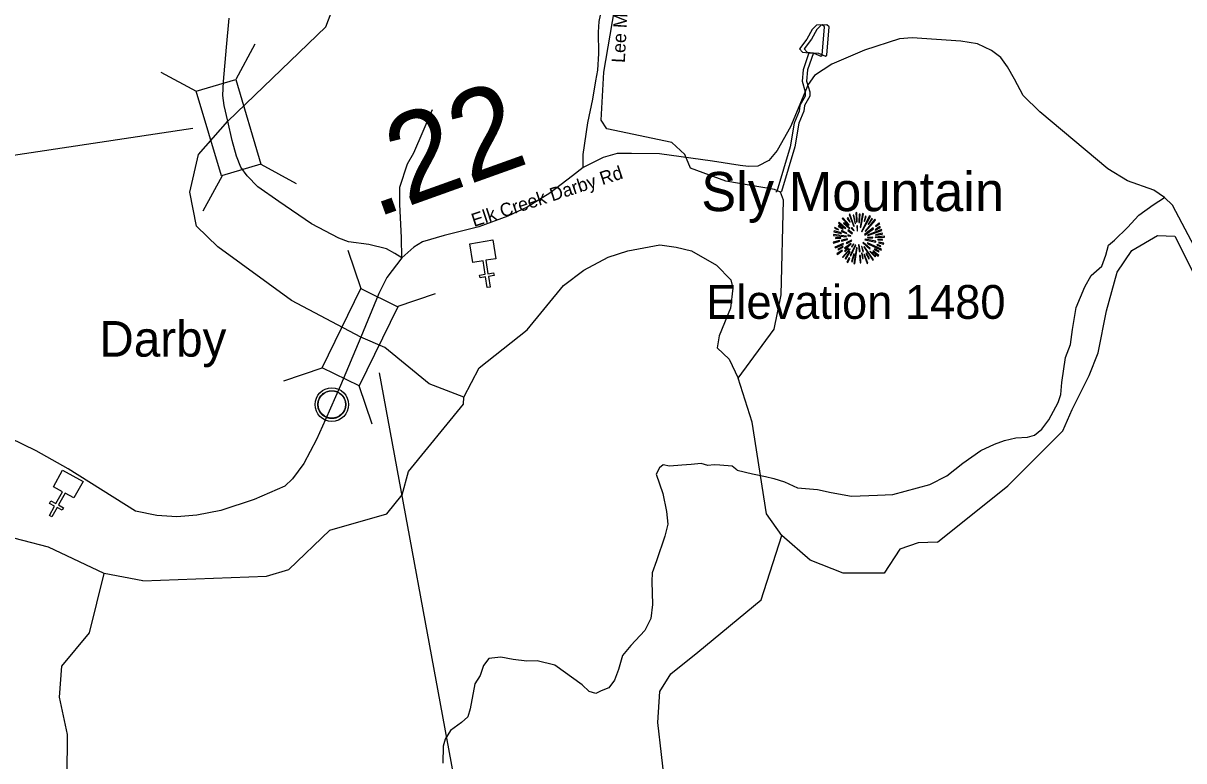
# Model space of a CAD drawing. Extents: x 1248089 to 1457196, y 820910 to 988753.
# Drawn here: x 1261020 to 1267538, y 869456 to 873600 of the extents above; entities that cross this region are included whole.
import ezdxf

# ---------------------------------------------------------------- set-up
doc = ezdxf.new("R2010")
doc.units = 0
for name, color, linetype in [('Exist Civil Demographics Community CELL', 7, 'Continuous'), ('Exist Civil Demographics Community Label', 7, 'Continuous'), ('Exist Cultural Church CELL', 7, 'Continuous'), ('Exist Geographical Mountain Summit CELL', 7, 'Continuous'), ('Exist Geographical Mountain Summit Elevation Number Label', 7, 'Continuous'), ('Exist Geographical Mountain Summit Label', 7, 'Continuous'), ('Exist Hydrographic Creek Single Shore', 7, 'Continuous'), ('Exist Hydrographic Misc Water Feature', 7, 'Continuous'), ('Exist Road Non-System Type 51', 7, 'Continuous'), ('Exist Road Secondary Structure Standard Bridge CELL', 7, 'Continuous'), ('Exist Road Secondary Structure Standard Bridge Number Label', 7, 'Continuous'), ('Exist Road Secondary Type 41 Attributed', 7, 'Continuous'), ('Exist Road Secondary Type 51 Attributed', 7, 'Continuous'), ('Exist Road Secondary Type 51 Label', 7, 'Continuous'), ('Prop GRAU CAT1 Cell', 7, 'Continuous')]:
    doc.layers.add(name, color=color, linetype=linetype)

msp = doc.modelspace()

# ---------------------------------------------------------------- linework, layer by layer
at = {"layer": 'Exist Civil Demographics Community CELL'}
msp.add_lwpolyline([(1262675.7, 871469.8), (1262676.7, 871475.4), (1262678.5, 871482), (1262681.4, 871489.2), (1262684.3, 871494.9), (1262687.6, 871500.7), (1262691.4, 871505.8), (1262695.4, 871510.2), (1262700, 871514.8), (1262705.5, 871519.4), (1262710.9, 871523), (1262715.8, 871525.9), (1262720.9, 871528.3), (1262726.3, 871530.6), (1262731.9, 871532.5), (1262736.3, 871533.6), (1262741.1, 871534.3), (1262745.3, 871535.1), (1262751.6, 871535.3), (1262756.1, 871535.2), (1262761.7, 871535), (1262766.6, 871534.2), (1262771.5, 871533.2), (1262776.5, 871531.8), (1262781.7, 871529.9), (1262788.4, 871527), (1262794.6, 871523.5), (1262799.7, 871519.9), (1262804.8, 871515.9), (1262808.2, 871512.8), (1262812.3, 871508.4), (1262816.1, 871503.7), (1262819.2, 871499.1), (1262822.3, 871494.1), (1262824.8, 871488.9), (1262826.8, 871483.9), (1262828.4, 871478.9), (1262829.7, 871474.3), (1262830.8, 871468.3), (1262831.4, 871463.6), (1262831.7, 871457.6), (1262831.5, 871451.8), (1262830.9, 871446.1), (1262830, 871440.6), (1262828.3, 871434.5), (1262826.4, 871428.6), (1262824.1, 871423.6), (1262821, 871417.6), (1262817.7, 871412.2), (1262814.3, 871407.5), (1262810, 871402.8), (1262804.7, 871397.8), (1262799.7, 871393.7), (1262794.7, 871390.3), (1262790.4, 871387.8), (1262783.6, 871384.5), (1262776.4, 871381.8), (1262770.5, 871380.4), (1262763.9, 871379.1), (1262759.4, 871378.6), (1262755, 871378.3), (1262749.4, 871378.3), (1262745.1, 871378.7), (1262739.5, 871379.5), (1262733.5, 871380.8), (1262728.9, 871382.1), (1262723.8, 871384), (1262719.2, 871385.9), (1262715.3, 871388.2), (1262708.5, 871392.3), (1262702.9, 871396.5), (1262698, 871401), (1262693.5, 871405.9), (1262690.3, 871409.8), (1262687.4, 871414), (1262683.3, 871421.1), (1262681.5, 871424.7), (1262679.8, 871428.7), (1262677.2, 871436.9), (1262675.7, 871443.9), (1262675, 871449.1), (1262674.7, 871455.4), (1262674.6, 871460.1), (1262675.2, 871466.6)], close=True, dxfattribs=at)
for centre, radius in [((1262753.3, 871457.4), 94.3), ((1262753, 871457.7), 76.7)]:
    msp.add_circle(centre, radius, dxfattribs=at)
at = {"layer": 'Exist Cultural Church CELL'}
for points in [[(1263674.5, 872276.8), (1263618.3, 872267.7), (1263630.4, 872192.5), (1263661.9, 872197.6), (1263664.5, 872181.8), (1263632.9, 872176.7), (1263642.4, 872117.4), (1263626.6, 872114.8), (1263617.1, 872174.2), (1263585.5, 872169.1), (1263582.9, 872184.9), (1263614.5, 872190), (1263602.5, 872265.1), (1263545.5, 872256.1), (1263528.6, 872361.2), (1263657.6, 872381.9)], [(1261304.6, 870932.6), (1261254.7, 870959.9), (1261218, 870893.2), (1261246.1, 870877.8), (1261238.4, 870863.8), (1261210.3, 870879.2), (1261181.4, 870826.4), (1261167.3, 870834.2), (1261196.3, 870886.9), (1261168.2, 870902.3), (1261175.9, 870916.3), (1261204, 870900.9), (1261240.6, 870967.6), (1261190.2, 870995.5), (1261241.4, 871088.8), (1261355.9, 871025.9)]]:
    msp.add_lwpolyline(points, close=True, dxfattribs=at)
at = {"layer": 'Exist Geographical Mountain Summit CELL'}
for points in [[(1265619.6, 872502.1), (1265655.5, 872464.7), (1265658.9, 872467.2), (1265623.6, 872506.9)], [(1265647.2, 872503.6), (1265662.8, 872481.8), (1265664.6, 872483.2), (1265651.2, 872507.6)], [(1265658.1, 872525.4), (1265684.3, 872458.5), (1265687.2, 872459.6), (1265663.2, 872527.9)], [(1265691.9, 872473.4), (1265694.4, 872474.1), (1265685.4, 872522.1), (1265681, 872521)], [(1265696.6, 872534.8), (1265700.7, 872482.8), (1265703.9, 872483.2), (1265702.5, 872535.9)], [(1265712.6, 872480.7), (1265716.6, 872480.7), (1265720.2, 872527.9), (1265714.8, 872527.9)], [(1265724.6, 872452.3), (1265739.5, 872529.4), (1265734, 872531.2), (1265721.3, 872453.1)], [(1265727.9, 872430.5), (1265730.8, 872428.7), (1265779.4, 872513.3), (1265774, 872517)], [(1265742.4, 872487.6), (1265745.7, 872486.4), (1265755.1, 872513.3), (1265750.4, 872515.1)], [(1265786.4, 872503.6), (1265765.3, 872470.1), (1265768.2, 872469), (1265790.7, 872500.3)], [(1265576.4, 872447.6), (1265598.8, 872438.9), (1265599.9, 872441.8), (1265577.8, 872452.7)], [(1265598.1, 872458.5), (1265623.9, 872442.1), (1265626.1, 872444.7), (1265601, 872462.5)], [(1265599.2, 872477.4), (1265638.8, 872446.9), (1265641, 872449.1), (1265602.9, 872481.8)], [(1265627.5, 872474.5), (1265660.3, 872445.4), (1265662.5, 872447.6), (1265630.5, 872479.6)], [(1265651.2, 872436), (1265676.3, 872417), (1265678.4, 872420), (1265653.7, 872439.2)], [(1265670.8, 872449.1), (1265684.7, 872432.6), (1265686.8, 872434.8), (1265674.1, 872452)], [(1265702.1, 872461.4), (1265703.5, 872432.3), (1265706.1, 872432.6), (1265706.1, 872461.8)], [(1265745.7, 872412), (1265747.5, 872409.5), (1265796.1, 872445.4), (1265792.9, 872449.8)], [(1265748.9, 872432), (1265751.1, 872429.8), (1265806.7, 872494.1), (1265802.7, 872498.8)], [(1265762.7, 872409.1), (1265763.8, 872406.9), (1265842, 872435.6), (1265840.2, 872440.3)], [(1265806.7, 872437.1), (1265834.3, 872452), (1265831.4, 872457), (1265805.3, 872439.6)], [(1265806.7, 872460), (1265808.6, 872457.4), (1265831.4, 872473.7), (1265827.8, 872477.4)], [(1265569.4, 872369.5), (1265570.8, 872364.4), (1265606.9, 872374.9), (1265604.7, 872378.2)], [(1265570.8, 872407.3), (1265642.8, 872400.3), (1265643.2, 872403.3), (1265570.8, 872412.3)], [(1265573.4, 872428.3), (1265614.8, 872418.9), (1265616, 872422.2), (1265574.6, 872433)], [(1265582.9, 872389.8), (1265612.6, 872391.3), (1265612.6, 872394.9), (1265581.8, 872394.9)], [(1265614.8, 872430.5), (1265645.4, 872418.5), (1265646.5, 872420.7), (1265617, 872434.6)], [(1265615.2, 872380.8), (1265616.3, 872376), (1265649.4, 872384.4), (1265648.7, 872388)], [(1265642.8, 872366.6), (1265645, 872361.8), (1265673.8, 872377.1), (1265672.7, 872380.4)], [(1265651.5, 872406.2), (1265668.6, 872404), (1265669, 872406.2), (1265652.3, 872410.5)], [(1265747.1, 872382.6), (1265807.8, 872370.6), (1265808.9, 872374.9), (1265748.2, 872386.2)], [(1265761.7, 872396.4), (1265761.7, 872393.5), (1265791.8, 872393.5), (1265792.5, 872398.5)], [(1265804.9, 872395.3), (1265857.3, 872398.5), (1265857.6, 872403.3), (1265805.3, 872398.5)], [(1265808.6, 872409.1), (1265845.3, 872415.6), (1265843.8, 872421.1), (1265807.1, 872411.3)], [(1265819.8, 872383.3), (1265846.3, 872381.1), (1265846.3, 872385.4), (1265820.2, 872386.5)], [(1265579.2, 872341.8), (1265581.8, 872337.2), (1265627.2, 872357.1), (1265625.7, 872361.8)], [(1265590.5, 872305.1), (1265593.4, 872301.1), (1265621.8, 872322.2), (1265619.2, 872325.5)], [(1265596.7, 872325.9), (1265625.7, 872342.6), (1265623.6, 872346.2), (1265594.5, 872330.9)], [(1265621.4, 872285.5), (1265624.3, 872283), (1265665, 872330.6), (1265662.1, 872332.7)], [(1265636.7, 872316.8), (1265655.9, 872334.9), (1265652.6, 872337.2), (1265632.3, 872320)], [(1265633, 872335.3), (1265635.9, 872331.6), (1265670.4, 872360), (1265668.6, 872362.6)], [(1265661.4, 872316.8), (1265636.3, 872277.5), (1265639.5, 872275), (1265665.4, 872314.6)], [(1265664.6, 872295.4), (1265669, 872293.6), (1265695.5, 872352), (1265693, 872352.8)], [(1265671.6, 872344.7), (1265674.8, 872341.8), (1265685, 872358.2), (1265683.1, 872359.6)], [(1265686.1, 872249.9), (1265690.8, 872248.8), (1265703.5, 872338.2), (1265700.3, 872339)], [(1265711.5, 872353.9), (1265715.5, 872316.8), (1265719.9, 872317.1), (1265714.8, 872354.6)], [(1265727.5, 872345.1), (1265736.2, 872315.3), (1265740.2, 872317.1), (1265729.7, 872346.2)], [(1265737.3, 872278.6), (1265731.9, 872308.5), (1265728.6, 872308.5), (1265733, 872277.5)], [(1265735.9, 872365.5), (1265774.4, 872330.2), (1265776.9, 872334.6), (1265737.7, 872367.7)], [(1265742, 872342.9), (1265792.5, 872268.1), (1265796.1, 872271), (1265744.6, 872344)], [(1265752.5, 872305.9), (1265768.6, 872276.4), (1265772.6, 872278.6), (1265756.3, 872307.3)], [(1265760.9, 872363), (1265839.1, 872324.8), (1265840.9, 872330.2), (1265762.4, 872365.8)], [(1265774.4, 872317.1), (1265804.5, 872288), (1265807.8, 872290.6), (1265776.6, 872319.6)], [(1265791.1, 872317.8), (1265821.6, 872292), (1265824.9, 872295.7), (1265792.9, 872320.4)], [(1265800.2, 872328.8), (1265825.3, 872315.7), (1265827.8, 872319.3), (1265802.4, 872332.7)], [(1265814.4, 872352.8), (1265835.4, 872344.7), (1265837.2, 872349.1), (1265815.8, 872356)], [(1265823.9, 872366.2), (1265852.1, 872358.9), (1265852.9, 872364.4), (1265824.9, 872370.6)], [(1265646.5, 872258.3), (1265651.2, 872255.4), (1265662.1, 872280.1), (1265658.9, 872282.3)], [(1265676.3, 872260.1), (1265688.3, 872302.9), (1265684.7, 872303.3), (1265671.9, 872261.1)], [(1265717.7, 872295.4), (1265721.3, 872252.9), (1265725.3, 872253.9), (1265722, 872295.4)], [(1265742, 872300.1), (1265759.5, 872250.3), (1265763.8, 872252.1), (1265745, 872300.8)]]:
    msp.add_lwpolyline(points, close=True, dxfattribs=at)
at = {"layer": 'Exist Hydrographic Creek Single Shore'}
msp.add_line((1261691.4, 870467.7), (1261475.5, 870508.2), dxfattribs=at)
for points in [[(1262169.1, 873050.1), (1262719.4, 873578.9), (1262773.4, 873722.3)], [(1262915.3, 871836.6), (1262526.2, 872042.9), (1262113.4, 872343.6), (1261994, 872460.2), (1261955.2, 872651), (1262003.6, 872863.1), (1262169.1, 873050.1)], [(1266154.9, 870684.7), (1266550.5, 871000.7), (1266858.5, 871309.7), (1266910.8, 871429.2), (1267006.1, 871620), (1267056.7, 871748.2), (1267104.4, 871983.7), (1267163.9, 872201.3), (1267247.3, 872323.5), (1267390.3, 872406.9), (1267488.6, 872403.9), (1267628.5, 872124.8)], [(1263494.4, 871498.5), (1263580.3, 871663.6), (1263849.9, 871878), (1264054.2, 872126.6), (1264169.4, 872212), (1264305.3, 872285.7), (1264415.9, 872320.3), (1264595.6, 872354.9), (1264687.8, 872341.1), (1264773, 872320.3), (1264913.5, 872239.6), (1264994.2, 872158.9), (1265005.7, 872110.5), (1264991.9, 871999.8), (1264929.7, 871843.1), (1264918.2, 871776.2), (1264985, 871711.6), (1265035.7, 871605.6)], [(1263494.4, 871498.5), (1263299.8, 871573.3), (1263051, 871778.5), (1262915.3, 871836.6)], [(1265281.7, 870721.6), (1265194.1, 870843.8), (1265114, 871358.9), (1265035.7, 871605.6)], [(1261691.4, 870467.7), (1262385.5, 870493.3), (1262511.4, 870530.2), (1262741.5, 870752), (1263061.5, 870844.1), (1263147.5, 870950.7), (1263183.5, 871081.2), (1263493.5, 871459.2), (1263494.4, 871498.5)], [(1261475.5, 870508.2), (1261162.5, 870655.7), (1260872.4, 870730.4), (1260813.5, 870786.7)], [(1266154.9, 870684.7), (1266046.6, 870680.1), (1265942.9, 870645.5), (1265855.4, 870509.5), (1265625, 870509.5), (1265440.7, 870583.3), (1265281.7, 870721.6)], [(1261646.5, 868709.1), (1261498.5, 868820.4), (1261375.5, 868982.3), (1261265.5, 869127.1), (1261269.5, 869603), (1261224.5, 869814), (1261237.4, 869987.8), (1261392.4, 870175), (1261475.5, 870508.2)]]:
    msp.add_lwpolyline(points, dxfattribs=at)
at = {"layer": 'Exist Hydrographic Misc Water Feature'}
for points in [[(1265035.7, 871605.6), (1265238.5, 871880.5), (1265276.4, 872073.5), (1265289.5, 872605), (1265272.9, 872651.2), (1265240.5, 872665.1), (1264966.5, 872713.3), (1264768.4, 872786.1), (1264736.4, 872862.2), (1264663.4, 872929.4), (1264298.4, 873005.7), (1264266.5, 873055.5), (1264280.4, 873324.4), (1264340.4, 873674.4)], [(1265432, 873432.9), (1265460.1, 873432.4), (1265499.7, 873415.1), (1265507.8, 873420.8), (1265519.7, 873578.9), (1265508, 873591.5), (1265475.8, 873588), (1265451.3, 873564.6), (1265422, 873509.5), (1265380.5, 873456.2), (1265396.1, 873437.7), (1265432, 873432.9)], [(1265458.1, 873432.9), (1265486.2, 873432.4), (1265525.8, 873415.1), (1265533.9, 873420.8), (1265545.8, 873578.9), (1265534.1, 873591.5), (1265501.9, 873588), (1265477.4, 873564.6), (1265448.1, 873509.5), (1265406.7, 873456.2), (1265422.2, 873437.7), (1265458.1, 873432.9)], [(1265432, 873432.9), (1265399.7, 873337.5), (1265394.1, 873273.7), (1265412.6, 873213.4), (1265412, 873189.6), (1265382.8, 873137.6), (1265378, 873105.7), (1265350.3, 873039), (1265327, 872904.9), (1265252.9, 872654.4), (1265246.7, 872651.2)], [(1265458.1, 873432.9), (1265425.8, 873337.5), (1265420.2, 873273.7), (1265438.7, 873213.4), (1265438.1, 873189.6), (1265408.9, 873137.6), (1265404.1, 873105.7), (1265376.4, 873039), (1265353.1, 872904.9), (1265279, 872654.4), (1265272.9, 872651.2)], [(1264624.6, 869312.6), (1264583.6, 869671.2), (1264595.6, 869845), (1264656.6, 869945.5), (1264809.5, 870067.2), (1265164.2, 870359.6), (1265281.7, 870721.6)]]:
    msp.add_lwpolyline(points, dxfattribs=at)
at = {"layer": 'Exist Road Non-System Type 51'}
for points in [[(1263147, 872281.4), (1263143.9, 872394.9), (1263134.7, 872584), (1263134.7, 872678.5), (1263178.4, 872809.9), (1263213, 872872.2), (1263319, 873114.3)], [(1265030.1, 871088.6), (1265115.3, 871067.9), (1265189.1, 871054), (1265235.1, 871042.5), (1265295, 871024.1), (1265368.8, 870989.5), (1265481.7, 870980.3), (1265557.7, 870964.1), (1265672.9, 870943.4), (1265818, 870948), (1265903.3, 870952.6), (1266112.9, 871007.9), (1266207.4, 871056.4), (1266297.3, 871127.8), (1266398.6, 871199.3), (1266476, 871235.4), (1266531.3, 871256.1), (1266595.8, 871269.9), (1266660.4, 871274.6), (1266699.5, 871286.1), (1266741, 871318.4), (1266780.2, 871371.4), (1266833.1, 871468.2), (1266847, 871514.3), (1266853.9, 871581.2), (1266874.6, 871721.8), (1266902.1, 871794.5), (1266913.6, 871879.8), (1266934.3, 872002), (1266982.7, 872119.5), (1267017.3, 872181.8), (1267077.2, 872234.8), (1267100.2, 872297.1), (1267116.3, 872352.4), (1267148.6, 872380.1), (1267222.3, 872451.6), (1267286.4, 872522.1), (1267367.1, 872579.7), (1267429.7, 872620.5)], [(1265030.1, 871088.6), (1265001.7, 871112.1), (1264932.6, 871116.8), (1264900.3, 871119.1), (1264865.7, 871114.4), (1264827.7, 871126.1), (1264772.4, 871121.5), (1264719.7, 871116.6), (1264649.2, 871112.1), (1264614.6, 871119.1), (1264594.1, 871102.4), (1264575.7, 871065.5), (1264612.3, 870957.7), (1264633, 870856.2), (1264639.9, 870784.7), (1264623.8, 870717.9), (1264577.7, 870579.5), (1264552.4, 870512.7), (1264550.3, 870463.3), (1264554.9, 870334.2), (1264545.7, 870255.8), (1264511.1, 870188.9), (1264432.8, 870103.6), (1264386.7, 870048.3), (1264363.6, 869969.9), (1264340.6, 869910), (1264308.3, 869866.2), (1264266.9, 869850), (1264236.9, 869833.9), (1264197.8, 869845.4), (1264158.6, 869882.3), (1264006.5, 869993), (1263907.5, 870018.3), (1263847.6, 870016), (1263771.5, 870025.2), (1263702.4, 870039.1), (1263635.6, 870029.9), (1263605.6, 869990.7), (1263587.2, 869935.3), (1263557.3, 869889.2), (1263529.6, 869748.6), (1263517, 869702.9), (1263482.4, 869670.6), (1263420.2, 869626.8), (1263390.3, 869578.4), (1263378.8, 869539.2), (1263376.5, 869442.4)]]:
    msp.add_lwpolyline(points, dxfattribs=at)
at = {"layer": 'Exist Road Secondary Structure Standard Bridge CELL'}
for p, q in [((1262321, 873482.3), (1262213.3, 873283.2)), ((1261792.3, 873324.8), (1261991.3, 873217.1)), ((1262353.8, 872807.7), (1262552.9, 872700)), ((1262136.8, 872743.1), (1262029.1, 872544.1)), ((1262917.8, 872108.3), (1262844.6, 872322.5)), ((1263121.1, 872008.6), (1263335.3, 872081.9)), ((1262484.5, 871590.3), (1262698.6, 871663.6)), ((1262979.8, 871347.5), (1262906.6, 871561.7))]:
    msp.add_line(p, q, dxfattribs=at)
for points in [[(1262213.3, 873283.2), (1262354.8, 872808.1), (1262132.9, 872742), (1261991.3, 873217.1)], [(1262698.6, 871663.6), (1262916.9, 872108.8), (1263124.8, 872006.8), (1262906.6, 871561.7)]]:
    msp.add_lwpolyline(points, close=True, dxfattribs=at)
at = {"layer": 'Exist Road Secondary Structure Standard Bridge Number Label'}
msp.add_line((1263018.9, 871635.9), (1263675.8, 868081.1), dxfattribs=at)
msp.add_lwpolyline([(1261972.1, 873008.7), (1258587.7, 872499.2), (1257259.5, 871971.5)], dxfattribs=at)
at = {"layer": 'Exist Road Secondary Type 41 Attributed'}
msp.add_lwpolyline([(1264164.6, 872789.4), (1264165.5, 872862.9), (1264191.9, 873039.5), (1264218.3, 873173.5), (1264236.5, 873277), (1264246.6, 873336.7), (1264252.7, 873430.1), (1264250.6, 873549.9), (1264254.7, 873608.7), (1264270.9, 873689.9), (1264281.1, 873724.4), (1264283.1, 873787.3), (1264270.9, 873894.9), (1264266.9, 873951.8), (1264273, 874046), (1264252.7, 874106.9), (1264258.8, 874154.7), (1264297.3, 874273.3), (1264311.5, 874363.8), (1264329.8, 874483.5), (1264313.6, 874615.5), (1264262.9, 874773.8), (1264271, 874842.8), (1264274.2, 874863.7)], dxfattribs=at)
at = {"layer": 'Exist Road Secondary Type 51 Attributed'}
for points in [[(1262169.1, 873050.1), (1262148.3, 873136.7), (1262141.7, 873193.7), (1262143.9, 873272.5), (1262161.4, 873465.3), (1262176.7, 873627.4)], [(1267699.4, 872151.6), (1267529.1, 872474.4), (1267474.3, 872577.9), (1267429.7, 872620.5), (1267370.9, 872661.1), (1267222.8, 872713.9), (1267112.4, 872781.9), (1266729, 873102.6), (1266635.8, 873194), (1266587.1, 873285.3), (1266548.5, 873354.3), (1266510, 873407.1), (1266459.3, 873445.7), (1266380.2, 873484.2), (1266286, 873498.5), (1266012.2, 873516.8), (1265941.2, 873512.7), (1265744.4, 873447.8), (1265561.9, 873370.6), (1265464.5, 873305.7), (1265428, 873254.9), (1265329.4, 873018.2), (1265254.3, 872884.2), (1265207.7, 872829.4), (1265146.8, 872796.9), (1265094.1, 872794.9), (1265047.5, 872801), (1264891.3, 872825.3), (1264593.1, 872865.9), (1264437, 872867.9), (1264355.8, 872867.9), (1264276.7, 872845.6), (1264164.6, 872789.4)], [(1263147, 872281.4), (1263108, 872306.1), (1263059.8, 872332.4), (1262961.4, 872356.5), (1262847.6, 872371.8), (1262792.8, 872391.5), (1262639.6, 872472.6), (1262455.8, 872597.4), (1262337.6, 872680.7), (1262278.6, 872742), (1262241.3, 872790.2), (1262217.3, 872853.7), (1262193.2, 872941.3), (1262169.1, 873050.1)], [(1264164.6, 872789.4), (1264105.8, 872742.7), (1263978, 872645.2), (1263850.2, 872566.1), (1263742.7, 872515.3), (1263578.4, 872456.5), (1263383.7, 872407.7), (1263262, 872371.2), (1263213.4, 872340.8), (1263147, 872281.4)], [(1263147, 872281.4), (1263062.2, 872171.8), (1263016.8, 872080.9), (1262915.3, 871836.6)], [(1262915.3, 871836.6), (1262802.8, 871565.4), (1262718.3, 871373.8), (1262667.2, 871262), (1262595.2, 871125.5), (1262532.8, 871040.3), (1262489.2, 870998.6), (1262316.9, 870924.7), (1262129.4, 870862.1), (1261994.2, 870835.4), (1261882.5, 870825.9), (1261770.8, 870833.5), (1261651.5, 870858.2), (1261272.8, 871096.9), (1261093.5, 871196.7), (1260721.3, 871376.7), (1260588.7, 871441.1), (1260408.8, 871507.4), (1260287.6, 871522.6)]]:
    msp.add_lwpolyline(points, dxfattribs=at)

# ---------------------------------------------------------------- texts
at = {"layer": 'Exist Civil Demographics Community Label'}
msp.add_text('Darby', height=200, dxfattribs=at).set_placement((1261447.8, 871726.6))
at = {"layer": 'Exist Geographical Mountain Summit Elevation Number Label'}
msp.add_text('Elevation 1480', height=190, dxfattribs=at).set_placement((1264856.1, 871938.9))
at = {"layer": 'Exist Geographical Mountain Summit Label'}
msp.add_text('Sly Mountain', height=220, dxfattribs=at).set_placement((1264828.4, 872544.1))
at = {"layer": 'Exist Road Secondary Type 51 Label'}
for s, rotation, p in [('Lee Mnt S Rd', 86.95895, (1264398.6, 873375.6)), ('Elk Creek Darby Rd', 18.0654, (1263551.7, 872454.6))]:
    msp.add_text(s, height=75, rotation=rotation, dxfattribs=at).set_placement(p)
at = {"layer": 'Prop GRAU CAT1 Cell'}
msp.add_text('.22', height=500, rotation=19.71299, dxfattribs=at).set_placement((1262997.8, 872504.5))

doc.saveas('drawing.dxf')
